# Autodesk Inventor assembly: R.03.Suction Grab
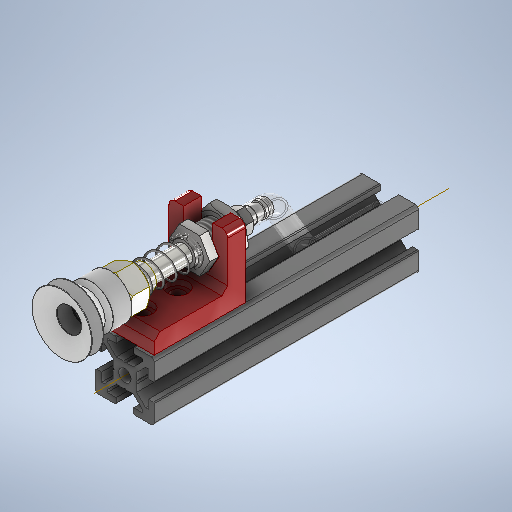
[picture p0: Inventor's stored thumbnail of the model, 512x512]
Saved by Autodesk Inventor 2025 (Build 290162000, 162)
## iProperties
Created: 2021-02
Part Number: R.03.Suction Grab
Document SubType Name: Assembly
Designer: Михальчик
Author: Михальчик
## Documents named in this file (11)
- C:\Users\Ryzen5700u\Desktop\robot_cicloidale_singolo\Workgroups\NotInProject\ventosa_20mm.iam
- C:\Users\Ryzen5700u\Desktop\robot_cicloidale_singolo\Workgroups\NotInProject\R.03.01.Cup.ipt
- C:\Users\Ryzen5700u\Desktop\robot_cicloidale_singolo\Workgroups\NotInProject\R.03.02.Tube.ipt
- C:\Users\Ryzen5700u\Desktop\robot_cicloidale_singolo\Workgroups\NotInProject\Compress Spring11.ipt
- C:\Users\Ryzen5700u\Desktop\robot_cicloidale_singolo\Workgroups\NotInProject\R.03.04.Fitting.ipt
- C:\Users\Ryzen5700u\Desktop\robot_cicloidale_singolo\Workgroups\NotInProject\DIN 3771 - 5 x 1,8 - N - NBR 70(2).ipt
- C:\Users\Ryzen5700u\Desktop\robot_cicloidale_singolo\Workgroups\NotInProject\R.03.05.Interface.ipt
- C:\Users\Ryzen5700u\Desktop\robot_cicloidale_singolo\Workgroups\NotInProject\R.03.06.Nut.ipt
- C:\Users\Ryzen5700u\Desktop\robot_cicloidale_singolo\Workgroups\NotInProject\blocco_ventosa_profilato.ipt
- C:\Users\Ryzen5700u\Desktop\robot_cicloidale_singolo\Workgroups\NotInProject\tubo_silicone.ipt
- C:\Users\Ryzen5700u\Desktop\robot_cicloidale_singolo\Workgroups\NotInProject\tslot-20x20-100mm.ipt
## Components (10 placed, 10 different names)
1. R.03.01.Cup:1 — Mate:1, Mate:2
2. R.03.02.Tube:1 — Mate:1, Mate:2, Mate:3, Flush:1, Mate:4, Mate:6, Rigido:1, Coincidente:12
3. R.03.03.Spring:1 — Mate:3, Flush:1, Mate:7
4. R.03.04.Fitting:1 — Mate:4, Rigido:1, Allineato:4
5. DIN 3771 - 5 x 1,8 - N - NBR 70(2):1 — Rotazionale:1
6. R.03.05.Interface:1 — Mate:6, Mate:7, Mate:8, Rotazionale:1, Angolo:2, Coincidente:11
7. R.03.06.Nut:1 — Mate:8, Coincidente:13
8. blocco_ventosa_profilato:1
9. tslot-20x20-100mm:1 — Coincidente:10, Allineato:2, Allineato:5
10. tubo_silicone:1 — Allineato:4
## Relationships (18: Mate 11, Flush 4, RevoluteJoint 1, WeldJoint 1, Angle 1)
- Mate:1: R.03.01.Cup:1 ↔ R.03.02.Tube:1
- Mate:2: R.03.01.Cup:1 ↔ R.03.02.Tube:1
- Mate:3: R.03.02.Tube:1 ↔ R.03.03.Spring:1
- Flush:1: R.03.02.Tube:1 ↔ R.03.03.Spring:1
- Mate:4: R.03.02.Tube:1 ↔ R.03.04.Fitting:1
- Mate:6: R.03.02.Tube:1 ↔ R.03.05.Interface:1
- Mate:7: R.03.03.Spring:1 ↔ R.03.05.Interface:1
- Mate:8: R.03.05.Interface:1 ↔ R.03.06.Nut:1
- Rotazionale:1 [RevoluteJoint]: DIN 3771 - 5 x 1,8 - N - NBR 70(2):1 ↔ R.03.05.Interface:1
- Rigido:1 [WeldJoint]: R.03.02.Tube:1 ↔ R.03.04.Fitting:1
- Coincidente:10 [Mate]: tslot-20x20-100mm:1
- Allineato:2 [Flush]: tslot-20x20-100mm:1
- Allineato:4 [Flush]: R.03.04.Fitting:1 ↔ tubo_silicone:1
- Angolo:2 [Angle]: R.03.05.Interface:1
- Coincidente:11 [Mate]: R.03.05.Interface:1
- Allineato:5 [Flush]: tslot-20x20-100mm:1
- Coincidente:12 [Mate]: R.03.02.Tube:1
- Coincidente:13 [Mate]: R.03.06.Nut:1
